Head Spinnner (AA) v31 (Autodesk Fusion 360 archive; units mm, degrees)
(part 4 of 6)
sketch "LED Light Direction Rig (LDR)" plane through (0, 0, 63.5) normal (0, 0, 1) x axis (-1, 0, 0)
  line L1 (-76.3312, 0) -> (-80.01, 0)
  line L2 (-83.6888, 0) -> (-80.01, 0)
  line L3 (-74.295, 0) -> (-76.3312, 0)
  line L4 (-85.725, 0) -> (-83.6888, 0)
  line L5 (-84.7122, 13.1383) -> (-79.1573, 11.6499)
  line L6 (-62.154, 10.16) -> (-73.597, 10.16)
  line L7 (-84.7122, -13.1383) -> (-73.597, -10.16)
  line L8 (-79.1573, 11.6499) -> (-73.597, 10.16)
  circle C1 centre (-49.8854, -62.5543) radius 3.6788
  circle C2 centre (72.0865, 34.715) radius 3.6788
  circle C3 centre (-80.01, 0) radius 3.6788
  circle C4 centre (17.8039, -78.004) radius 3.6788
  circle C5 centre (17.8039, 78.004) radius 3.6788
  circle C6 centre (-49.8854, 62.5543) radius 3.6788
  circle C7 centre (72.0865, -34.715) radius 3.6788
  circle C8 centre (0, 0) radius 42.164
  circle C9 centre (0, 0) radius 85.725
  circle C10 centre (0, 0) radius 74.295
  arc A1 centre (0, 0) radius 80.01 clockwise from (-79.9254, 3.6778) to (-79.1573, 11.6499)
  arc A2 centre (0, 0) radius 80.01 clockwise from (-79.9254, -3.6778) to (-79.9254, 3.6778)
  arc A3 centre (0, 0) radius 80.01 clockwise from (-79.1573, 11.6499) to (-79.1573, -11.6499)
  arc A4 centre (0, 0) radius 80.01 clockwise from (-79.1573, -11.6499) to (-79.9254, -3.6778)
  circle C11 centre (-79.6412, 7.6735) radius 1.5875
  circle C12 centre (-79.6412, -7.6735) radius 1.5875
  circle C13 centre (-79.6412, -7.6735) radius 1.5028
  circle C14 centre (-79.6412, 7.6735) radius 1.5028
  point P4 (-80.01, 0)
  point P10 (-80.01, 0)
  point P11 (-76.3312, 0)
  point P12 (-83.6888, 0)
  point P14 (-85.725, 0)
  point P1 (0, 0)
  point P15 (0, 0)
  point P13 (-74.295, 0)
  point P16 (-73.597, 10.16)
  point P19 (-73.597, -10.16)
  point P17 (-84.7122, 13.1383)
  point P20 (-84.7122, -13.1383)
  point P23 (-79.9254, 3.6778)
  point P25 (-79.9254, -3.6778)
  point P26 (-79.1573, -11.6499)
  point P29 (-79.6412, 7.6735)
  point P30 (-79.6412, -7.6735)
  coincident P4 P10
  coincident C3 P11
  horizontal L1
  coincident C3 P12
  parallel L1 L2
  parallel L1 L3
  coincident C9 P14
  parallel L2 L4
  equal L3 L4
  coincident P1 P15
  coincident P13 C10
  horizontal L6
  coincident C10 P16
  symmetric L2 P16 P19
  symmetric L2 P17 P20
  concentric C10 A2
  coincident P10 A2
  coincident C3 P23
  concentric A1 A2
  coincident C3 P25
  coincident L7 P26
  concentric A2 A3
  concentric A2 A4
  midpoint A1 P29
  midpoint A4 P30
  equal C11 C12
  coincident C9 P17
  dimension "d350" angle L5 L6 = 165
  dimension "d351" distance L1 L6 = 10.16
  dimension "d352" diameter C12 = 3.175
  dimension "d359" = -0.0847 (= "-clearance / 3")
  dimension "d360" = -0.0847 (= "d359")
extrude "Extrude5" new body sketch "LED Light Direction Rig (LDR)" profile of C3 C9 C10 L5 L7 L8 C11 C12 C13 C14 along normal blind 1.27
extrude "Extrude8" cut sketch "LED Light Direction Rig (LDR)" profile of C11 C12 C13 C14 against normal blind 6.35
extrude "Extrude14" add sketch "LED Light Direction Rig (LDR)" profile of C13 C14 against normal blind 2.54
extrude "Extrude15" add of existing geometry blind 3.81 taper -2.5
sketch "XY for LED (LDR)" plane through (0, 0, 64.77) normal (0, 0, 1) x axis (-1, 0, 0)
  line L1 (-84.7122, 13.1383) -> (-73.597, 10.16)
  line L2 (-73.597, -10.16) -> (-84.7122, -13.1383)
  line L3 (-85.5743, 5.08) -> (-74.1211, 5.08)
  line L4 (-80.01, -8.89) -> (-80.01, 0)
  line L5 (-69.85, 0) -> (-80.01, 0)
  line L6 (-85.5743, -5.08) -> (-74.1211, -5.08)
  circle C1 centre (-80.01, 0) radius 3.6788
  arc A1 centre (0, 0) radius 74.295 clockwise from (-73.597, -10.16) to (-73.597, 10.16)
  arc A2 centre (0, 0) radius 85.725 clockwise from (-84.7122, -13.1383) to (-84.7122, 13.1383)
  point P9 (-85.5743, 5.08)
  point P8 (-74.1211, 5.08)
  point P2 (-80.01, 0)
  point P10 (-80.01, 0)
  point P13 (-74.1211, -5.08)
  point P14 (-85.5743, -5.08)
  coincident A2 P9
  horizontal L3
  coincident A1 P8
  coincident P2 P10
  vertical L4
  perpendicular L4 L5
  symmetric P8 L5 P13
  symmetric P9 L5 P14
  dimension "d363" distance P2 L3 = 5.08
sketch "Z for LED (LDR)" plane through (0, 0, 0) normal (0, 1, 0) x axis (-1, 0, 0)
  line L1 (-76.2, 63.5) -> (-83.82, 63.5)
  line L2 (-77.51, 66.1543) -> (-82.51, 66.1543)
  line L3 (-82.9691, 58.3438) -> (-77.0509, 58.3438)
  line L4 (-77.0509, 68.6562) -> (-82.9691, 68.6562)
  line L5 (-80.01, 68.6562) -> (-80.01, 66.1543)
  line L6 (-36.8237, 247.2893) -> (-80.01, 67.4052)
  line L7 (-72.6354, 67.4052) -> (-80.01, 67.4052)
  line L8 (-73.2573, 69.0922) -> (-74.295, 64.77)
  line L9 (-82.0191, 80.2064) -> (-85.725, 64.77)
  line L10 (-73.2573, 69.0922) -> (-82.0191, 80.2064)
  line L11 (-39.211, 210.9055) -> (-73.2573, 69.0922)
  line L12 (-43.9341, 238.8415) -> (-82.0191, 80.2064)
  line L13 (-76.1619, 63.5) -> (-83.8581, 63.5)
  line L14 (-85.725, 63.5) -> (-84.7122, 63.5)
  line L15 (-84.7122, 64.77) -> (-84.7122, 63.5)
  line L16 (-85.725, 64.77) -> (-84.7122, 64.77)
  line L17 (-84.7122, 63.5) -> (-84.7122, 64.77)
  line L18 (-73.597, 64.77) -> (-74.295, 64.77)
  line L19 (-74.295, 64.77) -> (-85.725, 64.77)
  line L20 (-80.01, 66.1543) -> (-80.01, 64.77)
  point P10 (-80.01, 66.1543)
  point P11 (-80.01, 68.6562)
  point P12 (-80.01, 67.4052)
  point P16 (-85.725, 64.77)
  point P25 (-85.725, 64.77)
  point P26 (-74.295, 64.77)
  point P28 (-74.295, 64.77)
  point P29 (-85.725, 64.77)
  point P30 (-74.295, 64.77)
  point P31 (-80.01, 64.77)
  point P17 (-82.0191, 80.2064)
  point P15 (-73.2573, 69.0922)
  midpoint L2 P10
  midpoint L4 P11
  midpoint L5 P12
  parallel L6 L9
  parallel L6 L8
  parallel L6 L11
  parallel L9 L12
  coincident P16 P25
  coincident P26 P28
  coincident P25 P29
  coincident P26 P30
  midpoint L19 P31
  horizontal L7
  dimension "d368" angle L6 L7 = 76.5
  dimension "d369" distance P16 P17 = 15.875 (= "( 5 / 8 ) * 1 in")
  dimension "d370" distance P15 P26 = 4.445
sweep "Sweep1" sketch "Z for LED (LDR)" TwistAngle 0 TaperAngle 0
sketch "XY to Cut LED Path (LDR)" plane through (0, 0, 63.5) normal (0, 0, -1) x axis (1, 0, 0)
  line L1 (84.7122, -13.1383) -> (73.597, -10.16)
  line L2 (73.597, 10.16) -> (84.7122, 13.1383)
  circle C1 centre (80.01, 0) radius 3.6788
  arc A1 centre (0, 0) radius 74.295 clockwise from (73.597, 10.16) to (73.597, -10.16)
  arc A2 centre (0, 0) radius 85.725 clockwise from (84.7122, 13.1383) to (84.7122, -13.1383)
  circle C2 centre (80.01, 0) radius 3.6788
  circle C3 centre (80.01, 0) radius 4.1868
  circle C4 centre (79.6412, -7.6735) radius 1.5028
  circle C5 centre (79.6412, 7.6735) radius 1.5028
  concentric C1 C2
  tangent C1 C2
  dimension "d384" = 0.508
sketch "Z to Cut LED Path (LDR)" plane through (0, 0, 0) normal (0, 1, 0) x axis (1, 0, 0)
  line L1 (80.01, -68.6562) -> (80.01, -66.1543)
  line L2 (36.8237, -247.2893) -> (80.01, -67.4052)
  line L3 (80.01, -67.4052) -> (80.01, -66.1543)
  line L4 (78.2576, -74.7045) -> (80.01, -67.4053)
  line L5 (80.01, -63.5) -> (80.01, -66.1543)
  line L6 (73.4317, -69.4402) -> (73.1712, -69.2192)
  line L7 (75.8265, -69.2192) -> (73.1712, -69.2192)
  arc A1 centre (80.0096, -67.4052) radius 0.0004 clockwise from (80.01, -67.4052) to (80.01, -67.4053)
  arc A2 centre (80.0096, -67.4052) radius 0.236 clockwise from (80.01, -67.1692) to (80.01, -67.1692)
  point P2 (80.01, -66.1543)
  point P6 (80.01, -66.1543)
  point P7 (78.2576, -74.7045)
  point P10 (80.01, -67.4053)
  point P9 (80.01, -67.1692)
  point P4 (80.01, -67.4052)
  point P8 (80.01, -63.5)
  point P14 (80.01, -63.5)
  coincident P2 P6
  coincident L2 P7
  parallel L2 L4
  parallel L3 L5
  coincident L2 P10
  coincident L1 P9
  tangent L3 A1
  tangent L4 A1
  coincident P4 A1
  concentric A1 A2
  coincident P8 P14
  horizontal L7
sweep "Sweep2" sketch "XY to Cut LED Path (LDR)" TwistAngle 0 TaperAngle 0
work_plane "WorkPlane3"
sketch "Widen LDR" plane through (11.5879, 0, -9.1351) normal (-0.7853, 0, 0.6191) x axis (0, -1, 0)
  curve K1 (0, 102.7876) -> (0, 112.1565)
  curve K2 (0, 112.1565) -> (0, 102.7876)
  curve K3 (6.35, 107.2035) -> (-6.35, 107.2035)
  curve K4 (0, 112.1565) -> (0, 102.2505)
  closed curve K5 centre (0, 107.2035)
  point P5 (-6.35, 107.2035)
  point P6 (6.35, 107.2035)
  point P7 (0, 102.2505)
  point P8 (0, 112.1565)
  point P2 (0, 112.1565)
  point P9 (0, 112.1565)
  coincident K5 P5
  coincident K5 P6
  coincident K5 P7
  coincident K5 P8
  horizontal K3
  coincident P2 P9
  coincident P8 P9
  dimension "d388" distance K5 = 12.7
  dimension "d389" = 9.906
sweep "Sweep3" sketch "Widen LDR" TwistAngle 0 TaperAngle 0
sketch "LDR Foundation Fix" plane through (0, 0, 63.5) normal (0, 0, -1) x axis (1, 0, 0)
  line L1 (84.7122, -13.1383) -> (73.597, -10.16)
  line L2 (73.597, 10.16) -> (84.7122, 13.1383)
  line L3 (77.7639, -4.2594) -> (77.7639, -2.9134)
  line L4 (77.7639, 2.9134) -> (77.7639, 4.2594)
  arc A1 centre (0, 0) radius 74.295 clockwise from (73.597, 10.16) to (73.597, -10.16)
  arc A2 centre (0, 0) radius 85.725 clockwise from (84.7122, 13.1383) to (84.7122, -13.1383)
  closed curve K1 centre (80.7307, 0)
  arc A3 centre (80.01, 0) radius 3.6788 clockwise from (77.7639, 2.9134) to (77.7639, -2.9134)
  circle C1 centre (80.01, 0) radius 3.6788
  arc A4 centre (80.01, 0) radius 3.6788 clockwise from (76.9396, -2.0263) to (76.9396, 2.0263)
  closed curve K2 centre (80.7307, 0)
  circle C2 centre (79.6412, -7.6735) radius 1.5028
  circle C3 centre (79.6412, 7.6735) radius 1.5028
  concentric A3 C1
  tangent A3 C1
extrude "Extrude10" add sketch "LDR Foundation Fix" profile of A1 L1 A2 L2 L3 K1 L4 A3 C1 A4 K2 against normal blind 1.27
sketch "Sketch51" plane through (0, 0, 63.5) normal (0, 0, 1) x axis (-1, 0, 0)
  line L1 (-85.2717, -8.8044) -> (-73.9021, -7.6305)
  line L2 (-73.597, -10.16) -> (-84.7122, -13.1383)
  line L3 (-84.7122, -13.1383) -> (-73.597, -10.16)
  line L4 (-73.597, 10.16) -> (-84.7122, 13.1383)
  arc A1 centre (0, 0) radius 85.725 clockwise from (-84.7122, -13.1383) to (-85.2717, -8.8044)
  arc A2 centre (0, 0) radius 74.295 clockwise from (-73.597, -10.16) to (-73.9021, -7.6305)
  circle C1 centre (-80.01, 0) radius 3.8481
  circle C2 centre (-80.01, 0) radius 5.1181
  arc A3 centre (0, 0) radius 74.295 clockwise from (-73.597, -10.16) to (-73.597, 10.16)
  arc A4 centre (0, 0) radius 85.725 clockwise from (-84.7122, -13.1383) to (-84.7122, 13.1383)
  circle C3 centre (-80.01, 0) radius 3.6788
  circle C4 centre (-79.6412, -7.6735) radius 1.5028
  circle C5 centre (-79.6412, 7.6735) radius 1.5028
  dimension "d452" = 1.27
extrude "Extrude11" add sketch "Sketch51" profile of C1 C2 along normal blind 5.08
split "Split1"
remove_body "RemoveBody4"
component_from_bodies "Body->Comp3"
circular_pattern "C-Pattern1" TotalAngle 360
joint "Assemble17" alignAngle 10 alignOffsetX 0 alignOffsetY 0 alignOffsetZ 0
fillet "Fillet1" radius 2.54
chamfer "Chamfer1" distance 1.27
chamfer "Chamfer2" distance 1.27
fillet "Fillet2" radius 0.4763
chamfer "Chamfer3" distance 0.3175
step "C-Pattern" TotalAngle 360
copy_paste "CutPaste1"
copy_paste "CutPaste2"
copy_paste "CutPaste3"
copy_paste "CutPaste4"
copy_paste "CutPaste5"
copy_paste "CutPaste6"
copy_paste "CutPaste7"
copy_paste "CutPaste1"
copy_paste "CutPaste2"
copy_paste "CutPaste3"
copy_paste "CutPaste4"
chamfer "Chamfer1" distance 0.3175 distance 2.032
chamfer "Chamfer2" distance 1.8415
sketch "Bottom -> Shell Fastener" plane through (0, 0, -2.54) normal (0, 0, -1) x axis (1, 0, 0)
  line L1 (-41.7067, -40.7506) -> (-46.7095, -39.8685)
  line L2 (-39.1076, -31.4959) -> (-40.6033, -39.978)
  line L3 (-27.7068, -32.9614) -> (-37.1036, -30.2464)
  line L4 (17.4539, -40.93) -> (-27.6078, -32.9844)
  line L5 (17.4295, -50.2107) -> (18.7417, -42.769)
  line L6 (23.2049, -52.1963) -> (18.2021, -51.3142)
  line L7 (16.1071, -63.1959) -> (21.1099, -64.078)
  line L8 (13.6915, -71.4102) -> (15.0036, -63.9685)
  line L9 (-33.2094, -64.7523) -> (11.8524, -72.6979)
  line L10 (-43.0689, -64.0774) -> (-33.3102, -64.74)
  line L11 (-43.0291, -53.7358) -> (-44.5248, -62.2179)
  line L12 (-48.8046, -51.7502) -> (-43.8018, -52.6323)
  line L13 (20.1452, -83.3232) -> (19.2853, -80.2669)
  line L14 (26.2579, -81.6034) -> (20.1452, -83.3232)
  line L15 (25.398, -78.547) -> (26.2579, -81.6034)
  line L16 (19.2853, -80.2669) -> (25.398, -78.547)
  line L17 (26.2579, -81.6034) -> (19.2853, -80.2669)
  line L18 (19.3992, -80.3308) -> (25.3341, -78.661)
  line L19 (20.2091, -83.2093) -> (19.3992, -80.3308)
  line L20 (26.144, -81.5395) -> (20.2091, -83.2093)
  line L21 (25.3341, -78.661) -> (26.144, -81.5395)
  line L22 (22.7878, -80.9928) -> (22.7716, -80.9351)
  line L23 (0, 0) -> (22.7716, -80.9351)
  line L24 (-84.1375, 0) -> (0, 0)
  line L25 (-50.8026, -67.0687) -> (0, 0)
  line L26 (-85.6651, 3.175) -> (-85.6651, -3.175)
  line L27 (-85.6651, 3.175) -> (-82.4901, -3.175)
  line L28 (-85.5727, 3.0826) -> (-85.5727, -3.0826)
  line L29 (-82.4901, 3.175) -> (-85.6651, 3.175)
  line L30 (-82.5824, 3.0826) -> (-85.5727, 3.0826)
  line L31 (-82.5824, -3.0826) -> (-82.5824, 3.0826)
  line L32 (-82.4901, -3.175) -> (-82.4901, 3.175)
  line L33 (-85.5727, -3.0826) -> (-82.5824, -3.0826)
  line L34 (-85.6651, -3.175) -> (-82.4901, -3.175)
  line L35 (14.6103, 82.8593) -> (0, 0)
  line L36 (84.0329, 4.1939) -> (0, 0)
  line L37 (11.8237, 84.808) -> (11.3045, 81.8631)
  line L38 (14.6103, 82.8593) -> (14.5999, 82.8002)
  line L39 (17.3761, 80.7925) -> (17.8953, 83.7374)
  line L40 (18.0023, 83.8123) -> (11.1975, 81.7882)
  line L41 (18.0023, 83.8123) -> (11.7488, 84.915)
  line L42 (11.3045, 81.8631) -> (17.3761, 80.7925)
  line L43 (17.451, 80.6855) -> (18.0023, 83.8123)
  line L44 (11.1975, 81.7882) -> (17.451, 80.6855)
  line L45 (11.7488, 84.915) -> (11.1975, 81.7882)
  line L46 (17.8953, 83.7374) -> (11.8237, 84.808)
  line L47 (-8.4177, 54.7251) -> (26.6021, 48.5501)
  line L48 (30.8429, 72.6012) -> (-4.1768, 78.7761)
  circle C1 centre (-14.6103, -82.8593) radius 3.328
  circle C2 centre (84.0329, 4.1939) radius 3.328
  circle C3 centre (-22.7878, 80.9928) radius 3.328
  circle C4 centre (-73.8914, -40.2391) radius 3.328
  circle C5 centre (0, 0) radius 88.9
  circle C6 centre (-77.5307, 32.6819) radius 3.328
  circle C7 centre (49.1147, 68.3144) radius 3.328
  circle C8 centre (55.6726, -63.0847) radius 3.328
  arc A1 centre (-47.757, -45.8093) radius 6.0325 clockwise from (-48.8046, -51.7502) to (-46.7095, -39.8685)
  arc A2 centre (-41.5413, -39.8126) radius 0.9525 clockwise from (-40.6033, -39.978) to (-41.7067, -40.7506)
  arc A3 centre (-37.5443, -31.7715) radius 1.5875 clockwise from (-39.1076, -31.4959) to (-37.1036, -30.2464)
  arc A4 centre (-27.4424, -32.0464) radius 0.9525 clockwise from (-27.6078, -32.9844) to (-27.7068, -32.9614)
  arc A5 centre (17.1783, -42.4934) radius 1.5875 clockwise from (17.4539, -40.93) to (18.7417, -42.769)
  arc A6 centre (18.3675, -50.3761) radius 0.9525 clockwise from (18.2021, -51.3142) to (17.4295, -50.2107)
  arc A7 centre (22.1574, -58.1372) radius 6.0325 clockwise from (23.2049, -52.1963) to (21.1099, -64.078)
  arc A8 centre (15.9417, -64.1339) radius 0.9525 clockwise from (15.0036, -63.9685) to (16.1071, -63.1959)
  arc A9 centre (12.1281, -71.1345) radius 1.5875 clockwise from (13.6915, -71.4102) to (11.8524, -72.6979)
  arc A10 centre (-33.3748, -65.6903) radius 0.9525 clockwise from (-33.3102, -64.74) to (-33.2094, -64.7523)
  arc A11 centre (-42.9614, -62.4936) radius 1.5875 clockwise from (-43.0689, -64.0774) to (-44.5248, -62.2179)
  arc A12 centre (-43.9672, -53.5704) radius 0.9525 clockwise from (-43.8018, -52.6323) to (-43.0291, -53.7358)
  arc A13 centre (0, 0) radius 84.1375 clockwise from (-76.1776, 35.7224) to (-25.973, 80.0283)
  arc A14 centre (0, 0) radius 84.1375 clockwise from (-11.3221, -83.3722) to (-76.1776, 35.7224)
  arc A15 centre (0, 0) radius 84.1375 clockwise from (53.1343, -65.237) to (-11.3221, -83.3722)
  circle C9 centre (0, 0) radius 79.375
  arc A16 centre (0, 0) radius 84.1375 clockwise from (83.8013, 7.5138) to (53.1343, -65.237)
  arc A17 centre (0, 0) radius 84.1375 clockwise from (51.7779, 66.3187) to (83.8013, 7.5138)
  arc A18 centre (0, 0) radius 84.1375 clockwise from (46.3747, 70.2033) to (51.7779, 66.3187)
  arc A19 centre (0, 0) radius 84.1375 clockwise from (-25.973, 80.0283) to (-19.567, 81.8306)
  arc A20 centre (0, 0) radius 84.1375 clockwise from (-19.567, 81.8306) to (46.3747, 70.2033)
  arc A21 centre (28.7225, 60.5757) radius 12.2111 clockwise from (30.8429, 72.6012) to (26.6021, 48.5501)
  arc A22 centre (-6.2972, 66.7506) radius 12.2111 clockwise from (-8.4177, 54.7251) to (-4.1768, 78.7761)
  point P1 (0, 0)
  point P46 (0, 0)
  point P9 (55.6726, -63.0847)
  point P47 (-25.973, 80.0283)
  point P48 (-76.1776, 35.7224)
  point P50 (-11.3221, -83.3722)
  point P51 (53.1343, -65.237)
  point P54 (22.7878, -80.9928)
  point P60 (22.7716, -80.9351)
  point P61 (19.7153, -81.795)
  point P66 (25.8279, -80.0752)
  point P67 (22.7716, -80.9351)
  point P68 (22.7878, -80.9928)
  point P69 (0, 0)
  point P70 (0, 0)
  point P71 (-84.1375, 0)
  point P52 (0, 0)
  point P72 (0, 0)
  point P73 (-50.8026, -67.0687)
  point P56 (20.1452, -83.3232)
  point P74 (-85.6651, -3.175)
  point P57 (26.2579, -81.6034)
  point P75 (-85.6651, 3.175)
  point P58 (25.398, -78.547)
  point P79 (-82.4901, 3.175)
  point P59 (19.2853, -80.2669)
  point P76 (-82.4901, -3.175)
  point P62 (25.3341, -78.661)
  point P80 (-82.5824, 3.0826)
  point P63 (19.3992, -80.3308)
  point P81 (-82.5824, -3.0826)
  point P64 (20.2091, -83.2093)
  point P77 (-85.5727, -3.0826)
  point P65 (26.144, -81.5395)
  point P78 (-85.5727, 3.0826)
  point P82 (83.8013, 7.5138)
  point P83 (51.7779, 66.3187)
  point P88 (46.3747, 70.2033)
  point P89 (-19.567, 81.8306)
  point P87 (14.6103, 82.8593)
  point P85 (0, 0)
  point P86 (0, 0)
  point P53 (0, 0)
  point P92 (0, 0)
  point P93 (84.0329, 4.1939)
  point P94 (14.6103, 82.8593)
  point P101 (11.7488, 84.915)
  point P96 (18.0023, 83.8123)
  point P97 (17.451, 80.6855)
  point P102 (11.1975, 81.7882)
  point P99 (14.5999, 82.8002)
  point P100 (11.4732, 83.3516)
  point P103 (17.3761, 80.7925)
  point P105 (11.3045, 81.8631)
  point P107 (11.8237, 84.808)
  point P106 (17.8953, 83.7374)
  point P95 (17.7267, 82.2489)
  point P104 (14.5999, 82.8002)
  point P98 (14.6103, 82.8593)
  coincident P1 P46
  coincident P9 A14
  coincident C3 P47
  coincident C6 P48
  concentric A13 A14
  coincident C1 P50
  coincident C8 P51
  concentric A14 A16
  concentric A14 A15
  midpoint A15 P54
  perpendicular L13 L14
  perpendicular L14 L15
  perpendicular L13 L16
  midpoint L17 P60
  midpoint L13 P61
  coincident A15 P61
  midpoint L15 P66
  coincident A15 P66
  coincident P60 P67
  coincident P54 P68
  coincident P46 P69
  parallel L22 L23
  coincident P1 P70
  coincident A14 P71
  coincident P52 P72
  coincident A14 P73
  symmetric P56 L25 P74
  symmetric P57 L25 P75
  symmetric P58 L25 P79
  symmetric P59 L25 P76
  symmetric P62 L25 P80
  symmetric P63 L25 P81
  symmetric P64 L25 P77
  symmetric P65 L25 P78
  coincident C2 P82
  coincident C7 P83
  concentric A16 A18
  concentric A16 A17
  coincident C7 P88
  coincident C3 P89
  concentric A18 A19
  concentric A18 A20
  midpoint P87 A20
  coincident P85 P86
  horizontal L24
  coincident P53 P92
  coincident A17 P93
  symmetric P54 L36 P94
  symmetric P56 L36 P101
  symmetric P57 L36 P96
  symmetric P58 L36 P97
  symmetric P59 L36 P102
  symmetric P60 L36 P99
  symmetric P61 L36 P100
  symmetric P62 L36 P103
  symmetric P63 L36 P105
  symmetric P64 L36 P107
  symmetric P65 L36 P106
  symmetric P66 L36 P95
  symmetric P67 L36 P104
  symmetric P68 L36 P98
  dimension "d457" distance P56 P57 = 6.35
  dimension "d458" distance P56 P59 = 3.175
  dimension "d459" = -0.0924 (= "-clearance / 2.75")
  dimension "d462" angle L23 L24 = 105.714
  dimension "d463" angle L23 L25 = 52.857 (= "d462 / 2")
  dimension "d466" angle L23 L35 = 154.286
  dimension "d467" angle L35 L36 = 77.143 (= "d466 / 2")
extrude "Extrude33" add sketch "Bottom -> Shell Fastener" profile of L21 L20 L19 L18 L28 L30 L31 L33 L37 L39 L42 L46 against normal blind 6.35
extrude "Extrude9" sketch "Bottom -> Shell Fastener" profile of L13 L14 L15 L16 L21 L20 L19 L18 L26 L28 L29 L30 L31 L32 L33 L34 L37 L39 L41 L42 L43 L44 L45 L46 blind -5.08
chamfer "Chamfer5" distance 0.635
sketch "Pot Text" plane through (-88.9, 0, 0) normal (1, 0, 0) x axis (0, 1, 0)
  curve K1 (4.2549, 19.05) -> (4.2549, 19.05)
  curve K2 (0, 41.9735) -> (0, 34.2265)
  curve K3 (0, 34.2265) -> (0, 41.9735)
  line L1 (-88.9, 0) -> (88.9, 0)
  line L2 (-88.9, 60.325) -> (88.9, 60.325)
  curve K4 (-21.1365, 19.05) -> (-21.1365, 19.05)
  line L3 (-2.2914, 46.6515) -> (0, 38.1)
  line L4 (-5.08, 38.1) -> (0, 38.1)
  line L5 (-2.6201, 47.8782) -> (-2.2914, 46.6515)
  line L6 (-8.1873, 38.8117) -> (-8.8199, 38.8667)
  line L7 (-9.5625, 37.6564) -> (-8.1873, 38.8117)
  line L8 (-10.7178, 39.0316) -> (-9.5625, 37.6564)
  line L9 (-10.0851, 38.9766) -> (-10.7178, 39.0316)
  line L10 (-8.2117, 45.8633) -> (-8.8199, 38.8667)
  line L11 (-10.0851, 38.9766) -> (-8.8199, 38.8667)
  line L12 (-9.5625, 37.6564) -> (-9.4525, 38.9217)
  circle C1 centre (0, 38.1) radius 7.2644
  arc A1 centre (0, 38.1) radius 3.2703 clockwise from (-0.635, 34.892) to (-0.635, 41.308)
  circle C2 centre (0, 38.1) radius 8.8532
  arc A2 centre (0, 38.1) radius 8.8532 clockwise from (-8.8199, 38.8667) to (-2.2914, 46.6515)
  arc A3 centre (0, 38.1) radius 10.1232 clockwise from (-10.0851, 38.9766) to (-2.6201, 47.8782)
  point P18 (-8.8199, 38.8667)
  point P17 (-2.2914, 46.6515)
  point P19 (0, 38.1)
  point P20 (0, 38.1)
  point P12 (0, 38.1)
  point P21 (0, 38.1)
  point P31 (-9.4525, 38.9217)
  point P23 (-2.6201, 47.8782)
  point P25 (-2.6201, 47.8782)
  point P28 (-9.5625, 37.6564)
  concentric C1 A1
  coincident C2 P18
  coincident C2 P17
  coincident P19 P20
  coincident P12 P21
  horizontal L4
  coincident P12 P19
  parallel L3 L5
  perpendicular L7 L8
  tangent C2 L10
  equal L6 L9
  collinear L6 L9
  midpoint L11 P31
  perpendicular L11 L12
  coincident P23 P25
  dimension "d488" diameter C1 = 14.5288
  dimension "d489" = 1.5888
  dimension "d491" angle L3 L4 = 75
  dimension "d492" = 1.27
  dimension "d493" angle L6 L10 = 90
  dimension "d494" distance P28 P31 = 1.27
  dimension "d495" distance P17 P18 = 10.16
  dimension "d490" Text1-Height = 3.81
emboss "Emboss1" sketch "Pot Text" Depth -0.9525 Horizontal Distance 0 Vertical Distance 0 Rotation Angle 0
chamfer "Chamfer1" distance 1.524
sketch "Ref." plane through (0, 0, -2.54) normal (0, 0, -1) x axis (1, 0, 0)
  line L1 (-41.7067, -40.7506) -> (-46.7095, -39.8685)
  line L2 (-39.1076, -31.4959) -> (-40.6033, -39.978)
  line L3 (-27.7068, -32.9614) -> (-37.1036, -30.2464)
  line L4 (17.4539, -40.93) -> (-27.6078, -32.9844)
  line L5 (17.4295, -50.2107) -> (18.7417, -42.769)
  line L6 (23.2049, -52.1963) -> (18.2021, -51.3142)
  line L7 (16.1071, -63.1959) -> (21.1099, -64.078)
  line L8 (13.6915, -71.4102) -> (15.0036, -63.9685)
  line L9 (-33.2094, -64.7523) -> (11.8524, -72.6979)
  line L10 (-43.0689, -64.0774) -> (-33.3102, -64.74)
  line L11 (-43.0291, -53.7358) -> (-44.5248, -62.2179)
  line L12 (-48.8046, -51.7502) -> (-43.8018, -52.6323)
  line L13 (-8.4177, 54.7251) -> (26.6021, 48.5501)
  line L14 (30.8429, 72.6012) -> (-4.1768, 78.7761)
  circle C1 centre (-14.6103, -82.8593) radius 3.328
  circle C2 centre (84.0329, 4.1939) radius 3.328
  circle C3 centre (-22.7878, 80.9928) radius 3.328
  circle C4 centre (-73.8914, -40.2391) radius 3.328
  circle C5 centre (0, 0) radius 88.9
  circle C6 centre (-77.5307, 32.6819) radius 3.328
  circle C7 centre (49.1147, 68.3144) radius 3.328
  circle C8 centre (55.6726, -63.0847) radius 3.328
  arc A1 centre (-47.757, -45.8093) radius 6.0325 clockwise from (-48.8046, -51.7502) to (-46.7095, -39.8685)
  arc A2 centre (-41.5413, -39.8126) radius 0.9525 clockwise from (-40.6033, -39.978) to (-41.7067, -40.7506)
  arc A3 centre (-37.5443, -31.7715) radius 1.5875 clockwise from (-39.1076, -31.4959) to (-37.1036, -30.2464)
  arc A4 centre (-27.4424, -32.0464) radius 0.9525 clockwise from (-27.6078, -32.9844) to (-27.7068, -32.9614)
  arc A5 centre (17.1783, -42.4934) radius 1.5875 clockwise from (17.4539, -40.93) to (18.7417, -42.769)
  arc A6 centre (18.3675, -50.3761) radius 0.9525 clockwise from (18.2021, -51.3142) to (17.4295, -50.2107)
  arc A7 centre (22.1574, -58.1372) radius 6.0325 clockwise from (23.2049, -52.1963) to (21.1099, -64.078)
  arc A8 centre (15.9417, -64.1339) radius 0.9525 clockwise from (15.0036, -63.9685) to (16.1071, -63.1959)
  arc A9 centre (12.1281, -71.1345) radius 1.5875 clockwise from (13.6915, -71.4102) to (11.8524, -72.6979)
  arc A10 centre (-33.3748, -65.6903) radius 0.9525 clockwise from (-33.3102, -64.74) to (-33.2094, -64.7523)
  arc A11 centre (-42.9614, -62.4936) radius 1.5875 clockwise from (-43.0689, -64.0774) to (-44.5248, -62.2179)
  arc A12 centre (-43.9672, -53.5704) radius 0.9525 clockwise from (-43.8018, -52.6323) to (-43.0291, -53.7358)
  arc A13 centre (28.7225, 60.5757) radius 12.2111 clockwise from (30.8429, 72.6012) to (26.6021, 48.5501)
  arc A14 centre (-6.2972, 66.7506) radius 12.2111 clockwise from (-8.4177, 54.7251) to (-4.1768, 78.7761)
sketch "Remove 9V Battery" plane through (0, 0, 0) normal (0, 0, 1) x axis (-1, 0, 0)
  line L1 (-17.3761, 80.7925) -> (-11.3045, 81.8631)
  line L2 (-17.8953, 83.7374) -> (-17.3761, 80.7925)
  line L3 (-11.8237, 84.808) -> (-17.8953, 83.7374)
  line L4 (-11.3045, 81.8631) -> (-11.8237, 84.808)
  line L5 (85.5727, 3.0826) -> (82.5824, 3.0826)
  line L6 (85.5727, -3.0826) -> (85.5727, 3.0826)
  line L7 (82.5824, -3.0826) -> (85.5727, -3.0826)
  line L8 (82.5824, 3.0826) -> (82.5824, -3.0826)
  line L9 (-19.3992, -80.3308) -> (-25.3341, -78.661)
  line L10 (-20.2091, -83.2093) -> (-19.3992, -80.3308)
  line L11 (-26.144, -81.5395) -> (-20.2091, -83.2093)
  line L12 (-25.3341, -78.661) -> (-26.144, -81.5395)
  line L13 (-18.147, -51.6268) -> (-23.1498, -52.509)
  line L14 (-19.6797, -42.9344) -> (-18.147, -51.6268)
  line L15 (27.4424, -32.0464) -> (-17.6193, -39.992)
  line L16 (36.8392, -29.3314) -> (27.4424, -32.0464)
  line L17 (41.7618, -41.0633) -> (40.0457, -31.3305)
  line L18 (46.7646, -40.1812) -> (41.7618, -41.0633)
  line L19 (43.7466, -52.3197) -> (48.7494, -51.4375)
  line L20 (45.4628, -62.0525) -> (43.7466, -52.3197)
  line L21 (33.3748, -65.6903) -> (43.1334, -65.0277)
  line L22 (-11.687, -73.6359) -> (33.3748, -65.6903)
  line L23 (-16.1622, -62.8832) -> (-14.6295, -71.5756)
  line L24 (-21.165, -63.7653) -> (-16.1622, -62.8832)
  line L25 (-55.9395, 9.9372) -> (-55.803, 9.163)
  line L26 (-39.2687, 12.0784) -> (-39.4052, 12.8526)
  line L27 (-32.6329, -25.5549) -> (-32.7694, -24.7807)
  line L28 (-49.3038, -27.6962) -> (-49.1673, -28.4703)
  line L29 (-27.4486, 68.7829) -> (-24.3215, 51.0478)
  curve K1 (-27.4486, 68.7829) -> (-27.4528, 68.8072)
  curve K2 (-27.4528, 68.8072) -> (-25.9276, 70.9853)
  curve K3 (-25.9276, 70.9853) -> (-25.9034, 70.9897)
  line L30 (0.0613, 75.568) -> (-25.9034, 70.9897)
  curve K4 (0.0613, 75.568) -> (0.0856, 75.5721)
  curve K5 (0.0856, 75.5721) -> (2.2637, 74.047)
  curve K6 (2.2637, 74.047) -> (2.2681, 74.0227)
  line L31 (5.3953, 56.2877) -> (2.2681, 74.0227)
  curve K7 (5.3953, 56.2877) -> (5.3994, 56.2634)
  curve K8 (5.3994, 56.2634) -> (3.8743, 54.0853)
  curve K9 (3.8743, 54.0853) -> (3.8501, 54.0809)
  line L32 (-22.1146, 49.5026) -> (3.8501, 54.0809)
  curve K10 (-22.1146, 49.5026) -> (-22.1389, 49.4985)
  curve K11 (-22.1389, 49.4985) -> (-24.317, 51.0236)
  curve K12 (-24.317, 51.0236) -> (-24.3215, 51.0478)
  line L33 (-10.7789, -78.7861) -> (34.0078, -70.889)
  line L34 (34.0078, -70.889) -> (43.4877, -70.2453)
  line L35 (50.6129, -61.1444) -> (49.8047, -56.5607)
  line L36 (46.004, -35.0061) -> (45.1958, -30.4224)
  line L37 (35.3876, -24.3073) -> (26.2592, -26.9447)
  line L38 (26.2592, -26.9447) -> (-18.5275, -34.8418)
  line L39 (-24.8298, -43.8425) -> (-24.2051, -47.3858)
  line L40 (-20.4044, -68.9404) -> (-19.7796, -72.4837)
  arc A1 centre (-17.1783, -42.4934) radius 2.54 clockwise from (-19.6797, -42.9344) to (-17.6193, -39.992)
  arc A2 centre (37.5443, -31.7715) radius 2.54 clockwise from (36.8392, -29.3314) to (40.0457, -31.3305)
  arc A3 centre (47.757, -45.8093) radius 5.715 clockwise from (46.7646, -40.1812) to (48.7494, -51.4375)
  arc A4 centre (42.9614, -62.4936) radius 2.54 clockwise from (45.4628, -62.0525) to (43.1334, -65.0277)
  arc A5 centre (-12.1281, -71.1345) radius 2.54 clockwise from (-11.687, -73.6359) to (-14.6295, -71.5756)
  arc A6 centre (-22.1574, -58.1372) radius 5.715 clockwise from (-21.165, -63.7653) to (-23.1498, -52.509)
  circle C1 centre (14.6103, -82.8593) radius 1.804
  circle C2 centre (-49.1147, 68.3144) radius 1.804
  circle C3 centre (22.7878, 80.9928) radius 1.804
  circle C4 centre (-55.6726, -63.0847) radius 1.804
  circle C5 centre (73.8914, -40.2391) radius 1.804
  circle C6 centre (-84.0329, 4.1939) radius 1.804
  circle C7 centre (77.5307, 32.6819) radius 1.804
  circle C8 centre (0, 0) radius 88.9
  arc A7 centre (-44.2862, -7.8089) radius 20.5105 clockwise from (-49.3038, -27.6962) to (-55.803, 9.163)
  arc A8 centre (-47.6724, 11.3949) radius 8.3947 clockwise from (-55.9395, 9.9372) to (-39.4052, 12.8526)
  arc A9 centre (-44.2862, -7.8089) radius 20.5105 clockwise from (-39.2687, 12.0784) to (-32.7694, -24.7807)
  arc A10 centre (-40.9001, -27.0126) radius 8.3947 clockwise from (-32.6329, -25.5549) to (-49.1673, -28.4703)
  arc A11 centre (-12.1281, -71.1345) radius 7.7696 clockwise from (-10.7789, -78.7861) to (-19.7796, -72.4837)
  arc A12 centre (42.9614, -62.4936) radius 7.7696 clockwise from (50.6129, -61.1444) to (43.4877, -70.2453)
  arc A13 centre (47.757, -45.8093) radius 10.9446 clockwise from (46.004, -35.0061) to (49.8047, -56.5607)
  arc A14 centre (37.5443, -31.7715) radius 7.7696 clockwise from (35.3876, -24.3073) to (45.1958, -30.4224)
  arc A15 centre (-17.1783, -42.4934) radius 7.7696 clockwise from (-24.8298, -43.8425) to (-18.5275, -34.8418)
  arc A16 centre (-22.1574, -58.1372) radius 10.9446 clockwise from (-20.4044, -68.9404) to (-24.2051, -47.3858)
  dimension "d532" = -5.2296
extrude "Extrude35" cut sketch "Remove 9V Battery" profile of L13 L14 A1 L15 L16 A2 L17 L18 A3 L19 L20 A4 L21 L22 A5 L23 L24 A6 L34 A11 L36 L33 A14 L35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 along normal blind 30
extrude "Extrude36" add sketch "Remove 9V Battery" profile of L13 L14 A1 L15 L16 A2 L17 L18 A3 L19 L20 A4 L21 L22 A5 L23 L24 A6 L34 A11 L36 L33 A14 L35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 against normal blind 2.54
remove_instance "RemoveInstance7"
component_insert "Component Insert10"
position "Position13"
sketch "AA Battery Placement" plane through (0, 0, 0) normal (0, 0, 1) x axis (-1, 0, 0)
  line L1 (-17.3761, 80.7925) -> (-11.3045, 81.8631)
  line L2 (-17.8953, 83.7374) -> (-17.3761, 80.7925)
  line L3 (-11.8237, 84.808) -> (-17.8953, 83.7374)
  line L4 (-11.3045, 81.8631) -> (-11.8237, 84.808)
  line L5 (85.5727, 3.0826) -> (82.5824, 3.0826)
  line L6 (85.5727, -3.0826) -> (85.5727, 3.0826)
  line L7 (82.5824, -3.0826) -> (85.5727, -3.0826)
  line L8 (82.5824, 3.0826) -> (82.5824, -3.0826)
  line L9 (-19.3992, -80.3308) -> (-25.3341, -78.661)
  line L10 (-20.2091, -83.2093) -> (-19.3992, -80.3308)
  line L11 (-26.144, -81.5395) -> (-20.2091, -83.2093)
  line L12 (-25.3341, -78.661) -> (-26.144, -81.5395)
  line L13 (-55.9395, 9.9372) -> (-55.803, 9.163)
  line L14 (-39.2687, 12.0784) -> (-39.4052, 12.8526)
  line L15 (-32.6329, -25.5549) -> (-32.7694, -24.7807)
  line L16 (-49.3038, -27.6962) -> (-49.1673, -28.4703)
  line L17 (-27.4486, 68.7829) -> (-24.3215, 51.0478)
  curve K1 (-27.4486, 68.7829) -> (-27.4528, 68.8072)
  curve K2 (-27.4528, 68.8072) -> (-25.9276, 70.9853)
  curve K3 (-25.9276, 70.9853) -> (-25.9034, 70.9897)
  line L18 (0.0613, 75.568) -> (-25.9034, 70.9897)
  curve K4 (0.0613, 75.568) -> (0.0856, 75.5721)
  curve K5 (0.0856, 75.5721) -> (2.2637, 74.047)
  curve K6 (2.2637, 74.047) -> (2.2681, 74.0227)
  line L19 (5.3953, 56.2877) -> (2.2681, 74.0227)
  curve K7 (5.3953, 56.2877) -> (5.3994, 56.2634)
  curve K8 (5.3994, 56.2634) -> (3.8743, 54.0853)
  curve K9 (3.8743, 54.0853) -> (3.8501, 54.0809)
  line L20 (-22.1146, 49.5026) -> (3.8501, 54.0809)
  curve K10 (-22.1146, 49.5026) -> (-22.1389, 49.4985)
  curve K11 (-22.1389, 49.4985) -> (-24.317, 51.0236)
  curve K12 (-24.317, 51.0236) -> (-24.3215, 51.0478)
  line L21 (49.6903, -52.4861) -> (-7.1901, -62.5156)
  line L22 (-7.1901, -62.5156) -> (-8.2344, -62.6998)
  line L23 (-9.4631, -61.8394) -> (-9.6473, -60.7951)
  curve K13 (-9.4631, -61.8394) -> (-8.2344, -62.6998)
  line L24 (-9.6473, -60.7951) -> (-18.8433, -8.6418)
  line L25 (-18.8433, -8.6418) -> (-19.0274, -7.5975)
  line L26 (-18.1671, -6.3688) -> (-17.1228, -6.1846)
  curve K14 (-18.1671, -6.3688) -> (-19.0274, -7.5975)
  line L27 (-17.1228, -6.1846) -> (39.7576, 3.8449)
  line L28 (42.0306, 3.1687) -> (42.2148, 2.1244)
  curve K15 (42.0306, 3.1687) -> (40.8019, 4.0291)
  line L29 (39.7576, 3.8449) -> (40.8019, 4.0291)
  line L30 (42.2148, 2.1244) -> (51.4108, -50.0289)
  line L31 (51.4108, -50.0289) -> (51.595, -51.0732)
  line L32 (50.7346, -52.3019) -> (49.6903, -52.4861)
  curve K16 (50.7346, -52.3019) -> (51.595, -51.0732)
  line L33 (49.6903, -52.4861) -> (-7.1901, -62.5156)
  line L34 (49.8116, -53.174) -> (-7.0688, -63.2035)
  line L35 (50.8559, -52.9898) -> (49.8116, -53.174)
  curve K17 (50.8559, -52.9898) -> (52.2828, -50.9519)
  line L36 (52.0987, -49.9076) -> (52.2828, -50.9519)
  line L37 (42.9027, 2.2457) -> (52.0987, -49.9076)
  line L38 (42.7185, 3.29) -> (42.9027, 2.2457)
  curve K18 (42.7185, 3.29) -> (40.6806, 4.717)
  line L39 (39.6363, 4.5328) -> (40.6806, 4.717)
  line L40 (-17.244, -5.4967) -> (39.6363, 4.5328)
  line L41 (-18.2884, -5.6809) -> (-17.244, -5.4967)
  curve K19 (-18.2884, -5.6809) -> (-19.7153, -7.7188)
  line L42 (-19.5312, -8.7631) -> (-19.7153, -7.7188)
  line L43 (-10.3352, -60.9164) -> (-19.5312, -8.7631)
  line L44 (-10.151, -61.9607) -> (-10.3352, -60.9164)
  curve K20 (-10.151, -61.9607) -> (-8.1131, -63.3877)
  line L45 (-7.0688, -63.2035) -> (-8.1131, -63.3877)
  line L46 (51.297, -55.4912) -> (50.2526, -55.6754)
  curve K21 (51.297, -55.4912) -> (54.7843, -50.5109)
  line L47 (54.6001, -49.4665) -> (54.7843, -50.5109)
  line L48 (45.4041, 2.6867) -> (54.6001, -49.4665)
  line L49 (45.2199, 3.7311) -> (45.4041, 2.6867)
  curve K22 (45.2199, 3.7311) -> (40.2396, 7.2184)
  line L50 (39.1952, 7.0342) -> (40.2396, 7.2184)
  line L51 (-17.6851, -2.9953) -> (39.1952, 7.0342)
  line L52 (-18.7294, -3.1795) -> (-17.6851, -2.9953)
  curve K23 (-18.7294, -3.1795) -> (-22.2167, -8.1598)
  line L53 (-22.0326, -9.2042) -> (-22.2167, -8.1598)
  line L54 (-12.8366, -61.3575) -> (-22.0326, -9.2042)
  line L55 (-12.6524, -62.4018) -> (-12.8366, -61.3575)
  curve K24 (-12.6524, -62.4018) -> (-7.672, -65.8891)
  line L56 (-6.6277, -65.7049) -> (-7.672, -65.8891)
  line L57 (50.2526, -55.6754) -> (-6.6277, -65.7049)
  circle C1 centre (14.6103, -82.8593) radius 1.804
  circle C2 centre (-49.1147, 68.3144) radius 1.804
  circle C3 centre (22.7878, 80.9928) radius 1.804
  circle C4 centre (-55.6726, -63.0847) radius 1.804
  circle C5 centre (73.8914, -40.2391) radius 1.804
  circle C6 centre (-84.0329, 4.1939) radius 1.804
  circle C7 centre (77.5307, 32.6819) radius 1.804
  circle C8 centre (0, 0) radius 88.9
  arc A1 centre (-44.2862, -7.8089) radius 20.5105 clockwise from (-49.3038, -27.6962) to (-55.803, 9.163)
  arc A2 centre (-47.6724, 11.3949) radius 8.3947 clockwise from (-55.9395, 9.9372) to (-39.4052, 12.8526)
  arc A3 centre (-44.2862, -7.8089) radius 20.5105 clockwise from (-39.2687, 12.0784) to (-32.7694, -24.7807)
  arc A4 centre (-40.9001, -27.0126) radius 8.3947 clockwise from (-32.6329, -25.5549) to (-49.1673, -28.4703)
  dimension "d537" = -0.6985 (= "-clearance * 2.75")
  dimension "d538" = -3.2385 (= "d537 - 0.1 in")
extrude "Extrude38" cut sketch "AA Battery Placement" profile of L21 L22 L23 K13 L24 L25 L26 K14 L27 L28 K15 L29 L30 L31 L32 K16 L33 L41 L34 L35 L39 K17 L44 L36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 against normal blind 17.78
position "Position14"
extrude "Extrude39" add sketch "AA Battery Placement" profile of L41 L34 L35 L39 K17 L44 L36 K18 L45 L38 L37 L40 K19 L42 L43 K20 L51 L46 L50 K21 L55 L47 K22 L56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 along normal blind 15.24
sketch "AA ABattey Housing Top" plane through (0, 0, 15.24) normal (0, 0, 1) x axis (-1, 0, 0)
  line L1 (-19.7153, -7.7188) -> (-10.151, -61.9607)
  curve K1 (-18.2884, -5.6809) -> (-19.7153, -7.7188)
  line L2 (40.6806, 4.717) -> (-18.2884, -5.6809)
  curve K2 (42.7185, 3.29) -> (40.6806, 4.717)
  line L3 (52.2828, -50.9519) -> (42.7185, 3.29)
  curve K3 (50.8559, -52.9898) -> (52.2828, -50.9519)
  line L4 (-8.1131, -63.3877) -> (50.8559, -52.9898)
  curve K4 (-10.151, -61.9607) -> (-8.1131, -63.3877)
  line L5 (51.297, -55.4912) -> (-7.672, -65.8891)
  curve K5 (54.7843, -50.5109) -> (51.297, -55.4912)
  line L6 (45.2199, 3.7311) -> (54.7843, -50.5109)
  curve K6 (40.2396, 7.2184) -> (45.2199, 3.7311)
  line L7 (-18.7294, -3.1795) -> (40.2396, 7.2184)
  curve K7 (-22.2167, -8.1598) -> (-18.7294, -3.1795)
  line L8 (-12.6524, -62.4018) -> (-22.2167, -8.1598)
  curve K8 (-7.672, -65.8891) -> (-12.6524, -62.4018)
extrude "Extrude40" add sketch "AA ABattey Housing Top" along normal blind 2.54
joint "Assemble18" alignAngle 180 alignOffsetX 0 alignOffsetY 0 alignOffsetZ 0
sketch "AAA Housing Cut Out" plane through (0, 0, 17.78) normal (0, 0, 1) x axis (-1, 0, 0)
  curve K1 (-7.672, -65.8891) -> (-12.6524, -62.4018)
  line L1 (51.297, -55.4912) -> (-7.672, -65.8891)
  curve K2 (54.7843, -50.5109) -> (51.297, -55.4912)
  line L2 (45.2199, 3.7311) -> (54.7843, -50.5109)
  curve K3 (40.2396, 7.2184) -> (45.2199, 3.7311)
  line L3 (-18.7294, -3.1795) -> (40.2396, 7.2184)
  curve K4 (-22.2167, -8.1598) -> (-18.7294, -3.1795)
  line L4 (-12.6524, -62.4018) -> (-22.2167, -8.1598)
  line L5 (5.2965, -58.5877) -> (-4.0458, -5.605)
  line L6 (-7.9, -60.9146) -> (5.2965, -58.5877)
  line L7 (-17.2422, -7.9319) -> (-7.9, -60.9146)
  line L8 (-4.0458, -5.605) -> (-17.2422, -7.9319)
  line L9 (27.2711, -0.083) -> (36.6133, -53.0657)
  line L10 (40.4675, 2.2439) -> (27.2711, -0.083)
  line L11 (49.8098, -50.7388) -> (40.4675, 2.2439)
  line L12 (36.6133, -53.0657) -> (49.8098, -50.7388)
  line L13 (3.5467, -44.567) -> (-0.8947, -19.3786)
  line L14 (33.4622, -39.2921) -> (3.5467, -44.567)
  line L15 (29.0208, -14.1037) -> (33.4622, -39.2921)
  line L16 (-0.8947, -19.3786) -> (29.0208, -14.1037)
  line L17 (38.8988, -4.302) -> (-13.5294, -13.5465)
  line L18 (40.8393, -15.3067) -> (38.8988, -4.302)
  line L19 (12.6847, -8.9242) -> (14.0631, -16.7411)
  line L20 (-11.5889, -24.5512) -> (-13.5294, -13.5465)
  line L21 (-0.3326, -22.5664) -> (-11.5889, -24.5512)
  line L22 (29.5829, -17.2915) -> (40.8393, -15.3067)
  line L23 (21.3434, -28.4432) -> (31.2415, -26.6979)
  line L24 (21.3434, -28.4432) -> (31.2415, -26.6979)
  line L25 (32.9001, -36.1043) -> (44.1565, -34.1195)
  line L26 (44.1565, -34.1195) -> (46.0969, -45.1242)
  line L27 (46.0969, -45.1242) -> (-6.3313, -54.3687)
  line L28 (-8.2717, -43.364) -> (-6.3313, -54.3687)
  line L29 (2.9846, -41.3792) -> (-8.2717, -43.364)
  circle C1 centre (-5.9729, -33.2598) radius 1.5
  circle C2 centre (38.5358, -25.3848) radius 1.5
  circle C3 centre (38.5358, -25.3848) radius 1.45
  circle C4 centre (-5.9729, -33.2598) radius 1.45
  point P27 (14.0631, -16.7411)
  point P28 (12.6847, -8.9242)
  point P30 (-0.3326, -22.5664)
  point P31 (29.5829, -17.2915)
  point P32 (31.2415, -26.6979)
  point P24 (-13.5294, -13.5465)
  point P39 (-6.3313, -54.3687)
  point P25 (38.8988, -4.302)
  point P38 (46.0969, -45.1242)
  point P26 (40.8393, -15.3067)
  point P36 (44.1565, -34.1195)
  point P29 (-11.5889, -24.5512)
  point P40 (-8.2717, -43.364)
  point P41 (2.9846, -41.3792)
  point P37 (32.9001, -36.1043)
  point P34 (31.2415, -26.6979)
  point P33 (21.3434, -28.4432)
  point P35 (21.3434, -28.4432)
  point P19 (38.5358, -25.3848)
  perpendicular L9 L17
  perpendicular L17 L18
  midpoint L16 P27
  midpoint L17 P28
  perpendicular L17 L19
  perpendicular L17 L20
  coincident L13 P30
  perpendicular L13 L21
  coincident L15 P31
  perpendicular L15 L22
  collinear L21 L22
  midpoint L15 P32
  perpendicular L15 L23
  symmetric P24 L23 P39
  symmetric P25 L23 P38
  symmetric P26 L23 P36
  symmetric P29 L23 P40
  symmetric P30 L23 P41
  symmetric P31 L23 P37
  symmetric P32 L23 P34
  symmetric P33 L23 P35
  concentric C2 C3
  concentric C1 C4
  equal C3 C4
  dimension "d551" = -19.05
  dimension "d552" distance L2 L18 = 7.62
  dimension "d553" distance L3 L17 = 11.1125 (= "( 3.5 / 8 ) * 1 in")
  dimension "d559" distance P19 L22 = 9.525
  dimension "d560" diameter C3 = 2.9
extrude "Extrude41" cut sketch "AAA Housing Cut Out" profile of L13 L15 L17 L18 L20 L21 L22 L25 L26 L27 L28 L29 C3 C4 against normal blind 30.48
fillet "Fillet6" radius 1.27
sketch "Battery Cover Cut Out" plane through (0, 0, -2.54) normal (0, 0, -1) x axis (1, 0, 0)
  curve K1 (8.1131, -63.3877) -> (10.151, -61.9607)
  line L1 (-50.8559, -52.9898) -> (8.1131, -63.3877)
  curve K2 (-52.2828, -50.9519) -> (-50.8559, -52.9898)
  line L2 (-42.7185, 3.29) -> (-52.2828, -50.9519)
  curve K3 (-40.6806, 4.717) -> (-42.7185, 3.29)
  line L3 (18.2884, -5.6809) -> (-40.6806, 4.717)
  curve K4 (19.7153, -7.7188) -> (18.2884, -5.6809)
  line L4 (10.151, -61.9607) -> (19.7153, -7.7188)
  line L5 (-8.4177, 54.7251) -> (26.6021, 48.5501)
  line L6 (30.8429, 72.6012) -> (-4.1768, 78.7761)
  line L7 (-44.9073, 3.6759) -> (-54.4716, -50.566)
  curve K5 (-40.2947, 6.9057) -> (-44.9073, 3.6759)
  line L8 (18.6743, -3.4921) -> (-40.2947, 6.9057)
  curve K6 (21.9041, -8.1047) -> (18.6743, -3.4921)
  line L9 (12.3397, -62.3466) -> (21.9041, -8.1047)
  curve K7 (7.7272, -65.5764) -> (12.3397, -62.3466)
  line L10 (-51.2418, -55.1786) -> (7.7272, -65.5764)
  curve K8 (-54.4716, -50.566) -> (-51.2418, -55.1786)
  line L11 (-54.6922, -22.5629) -> (-49.6894, -23.445)
  line L12 (-23.2257, -68.705) -> (-21.7573, -60.3775)
  line L13 (-44.9073, 3.6759) -> (-59.5606, -21.7045)
  line L14 (-59.5606, -21.7045) -> (-54.4716, -50.566)
  line L15 (-54.6922, -22.5629) -> (-59.5606, -21.7045)
  line L16 (26.9931, -36.9662) -> (12.3397, -62.3466)
  line L17 (21.9041, -8.1047) -> (26.9931, -36.9662)
  arc A1 centre (28.7225, 60.5757) radius 12.2111 clockwise from (30.8429, 72.6012) to (26.6021, 48.5501)
  arc A2 centre (-6.2972, 66.7506) radius 12.2111 clockwise from (-8.4177, 54.7251) to (-4.1768, 78.7761)
  circle C1 centre (55.6726, -63.0847) radius 3.328
  circle C2 centre (49.1147, 68.3144) radius 3.328
  circle C3 centre (-77.5307, 32.6819) radius 3.328
  circle C4 centre (0, 0) radius 88.9
  circle C5 centre (-73.8914, -40.2391) radius 3.328
  circle C6 centre (-22.7878, 80.9928) radius 3.328
  circle C7 centre (84.0329, 4.1939) radius 3.328
  circle C8 centre (-14.6103, -82.8593) radius 3.328
  circle C9 centre (-54.6922, -22.5629) radius 1.5
  circle C10 centre (22.1247, -36.1078) radius 1.5
  point P32 (-49.6894, -23.445)
  point P34 (-21.7573, -60.3775)
  point P33 (-54.6922, -22.5629)
  point P36 (-54.6922, -22.5629)
  point P38 (-54.6922, -22.5629)
  point P24 (-54.4716, -50.566)
  point P39 (12.3397, -62.3466)
  point P25 (-44.9073, 3.6759)
  point P41 (21.9041, -8.1047)
  point P37 (-59.5606, -21.7045)
  point P40 (26.9931, -36.9662)
  midpoint L7 P32
  perpendicular L7 L11
  midpoint L10 P34
  perpendicular L10 L12
  coincident P33 P36
  coincident P36 P38
  parallel L11 L15
  symmetric P24 L12 P39
  symmetric P25 L12 P41
  symmetric L12 C9 C10
  symmetric L12 P37 P40
  dimension "d561" = -2.2225
  dimension "d562" diameter C9 = 3
  dimension "d563" angle L7 L14 = 20
  dimension "d564" distance P32 P33 = 5.08
extrude "Extrude42" cut sketch "Battery Cover Cut Out" profile of K1 L1 K2 L2 K3 L3 K4 L4 K8 K7 K6 L8 L10 K5 C9 L13 L14 L16 L17 C10 against normal blind 1.905
fillet "Fillet7" radius 2.54
sketch "Battery Cover" plane through (0, 0, -2.54) normal (0, 0, -1) x axis (1, 0, 0)
  curve K1 (21.9445, -7.8065) -> (21.9717, -8.4882)
  line L1 (26.8326, -36.0558) -> (21.9717, -8.4882)
  line L2 (12.5356, -62.0074) -> (26.5309, -37.7669)
  curve K2 (12.5356, -62.0074) -> (12.2752, -62.6453)
  curve K3 (7.7272, -65.5764) -> (12.2752, -62.6453)
  line L3 (-51.2418, -55.1786) -> (7.7272, -65.5764)
  curve K4 (-54.512, -50.8642) -> (-51.2418, -55.1786)
  curve K5 (-54.512, -50.8642) -> (-54.5392, -50.1825)
  line L4 (-59.4001, -22.6149) -> (-54.5392, -50.1825)
  line L5 (-45.1031, 3.3367) -> (-59.0984, -20.9038)
  curve K6 (-45.1031, 3.3367) -> (-44.8427, 3.9746)
  curve K7 (-40.2947, 6.9057) -> (-44.8427, 3.9746)
  line L6 (18.6743, -3.4921) -> (-40.2947, 6.9057)
  curve K8 (21.9445, -7.8065) -> (18.6743, -3.4921)
  line L7 (-8.4177, 54.7251) -> (26.6021, 48.5501)
  line L8 (30.8429, 72.6012) -> (-4.1768, 78.7761)
  curve K9 (-44.8832, 3.2097) -> (-44.5967, 3.9114)
  line L9 (-44.8832, 3.2097) -> (-58.8784, -21.0308)
  line L10 (-59.15, -22.5708) -> (-54.2891, -50.1384)
  curve K10 (-54.2592, -50.8882) -> (-54.2891, -50.1384)
  curve K11 (-54.2592, -50.8882) -> (-51.1977, -54.9284)
  line L11 (-51.1977, -54.9284) -> (7.7713, -65.3262)
  curve K12 (7.7713, -65.3262) -> (12.0292, -62.5821)
  curve K13 (12.3156, -61.8804) -> (12.0292, -62.5821)
  line L12 (12.3156, -61.8804) -> (26.3109, -37.6399)
  line L13 (26.5824, -36.0999) -> (21.7215, -8.5323)
  curve K14 (21.6916, -7.7825) -> (21.7215, -8.5323)
  curve K15 (21.6916, -7.7825) -> (18.6302, -3.7423)
  line L14 (18.6302, -3.7423) -> (-40.3388, 6.6555)
  curve K16 (-40.3388, 6.6555) -> (-44.5967, 3.9114)
  arc A1 centre (24.3312, -36.4969) radius 2.54 clockwise from (26.8326, -36.0558) to (26.5309, -37.7669)
  arc A2 centre (-56.8987, -22.1738) radius 2.54 clockwise from (-59.4001, -22.6149) to (-59.0984, -20.9038)
  arc A3 centre (28.7225, 60.5757) radius 12.2111 clockwise from (30.8429, 72.6012) to (26.6021, 48.5501)
  arc A4 centre (-6.2972, 66.7506) radius 12.2111 clockwise from (-8.4177, 54.7251) to (-4.1768, 78.7761)
  circle C1 centre (55.6726, -63.0847) radius 3.328
  circle C2 centre (49.1147, 68.3144) radius 3.328
  circle C3 centre (-77.5307, 32.6819) radius 3.328
  circle C4 centre (0, 0) radius 88.9
  circle C5 centre (-73.8914, -40.2391) radius 3.328
  circle C6 centre (-22.7878, 80.9928) radius 3.328
  circle C7 centre (84.0329, 4.1939) radius 3.328
  circle C8 centre (-14.6103, -82.8593) radius 3.328
  arc A5 centre (-56.8987, -22.1738) radius 2.286 clockwise from (-59.15, -22.5708) to (-58.8784, -21.0308)
  arc A6 centre (24.3312, -36.4969) radius 2.286 clockwise from (26.5824, -36.0999) to (26.3109, -37.6399)
  dimension "d569" = 0.254 (= "clearance")
extrude "Extrude12" new body sketch "Battery Cover" profile of K16 K15 K14 A5 K10 A6 L12 K13 L11 K12 L10 L14 L9 K11 L13 K9 against normal blind 1.5494 (magnitude of "-0.061 * 1 in")
sketch "Battery Cover Holes" plane through (0, 0, -2.54) normal (0, 0, -1) x axis (1, 0, 0)
  line L1 (-54.2891, -50.1384) -> (-59.15, -22.5708)
  curve K1 (-54.2592, -50.8882) -> (-54.2891, -50.1384)
  curve K2 (-54.2592, -50.8882) -> (-51.1977, -54.9284)
  line L2 (7.7713, -65.3262) -> (-51.1977, -54.9284)
  curve K3 (7.7713, -65.3262) -> (12.0292, -62.5821)
  curve K4 (12.3156, -61.8804) -> (12.0292, -62.5821)
  line L3 (26.3109, -37.6399) -> (12.3156, -61.8804)
  line L4 (21.7215, -8.5323) -> (26.5824, -36.0999)
  curve K5 (21.6916, -7.7825) -> (21.7215, -8.5323)
  curve K6 (21.6916, -7.7825) -> (18.6302, -3.7423)
  line L5 (-40.3388, 6.6555) -> (18.6302, -3.7423)
  curve K7 (-40.3388, 6.6555) -> (-44.5967, 3.9114)
  curve K8 (-44.8832, 3.2097) -> (-44.5967, 3.9114)
  line L6 (-58.8784, -21.0308) -> (-44.8832, 3.2097)
  arc A1 centre (-56.8987, -22.1738) radius 2.286 clockwise from (-59.15, -22.5708) to (-58.8784, -21.0308)
  arc A2 centre (24.3312, -36.4969) radius 2.286 clockwise from (26.5824, -36.0999) to (26.3109, -37.6399)
  circle C1 centre (-54.6922, -22.5629) radius 1.5
  circle C2 centre (22.1247, -36.1078) radius 1.5
extrude "Extrude13" cut sketch "Battery Cover Holes" profile of C1 C2 against normal blind 12.7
